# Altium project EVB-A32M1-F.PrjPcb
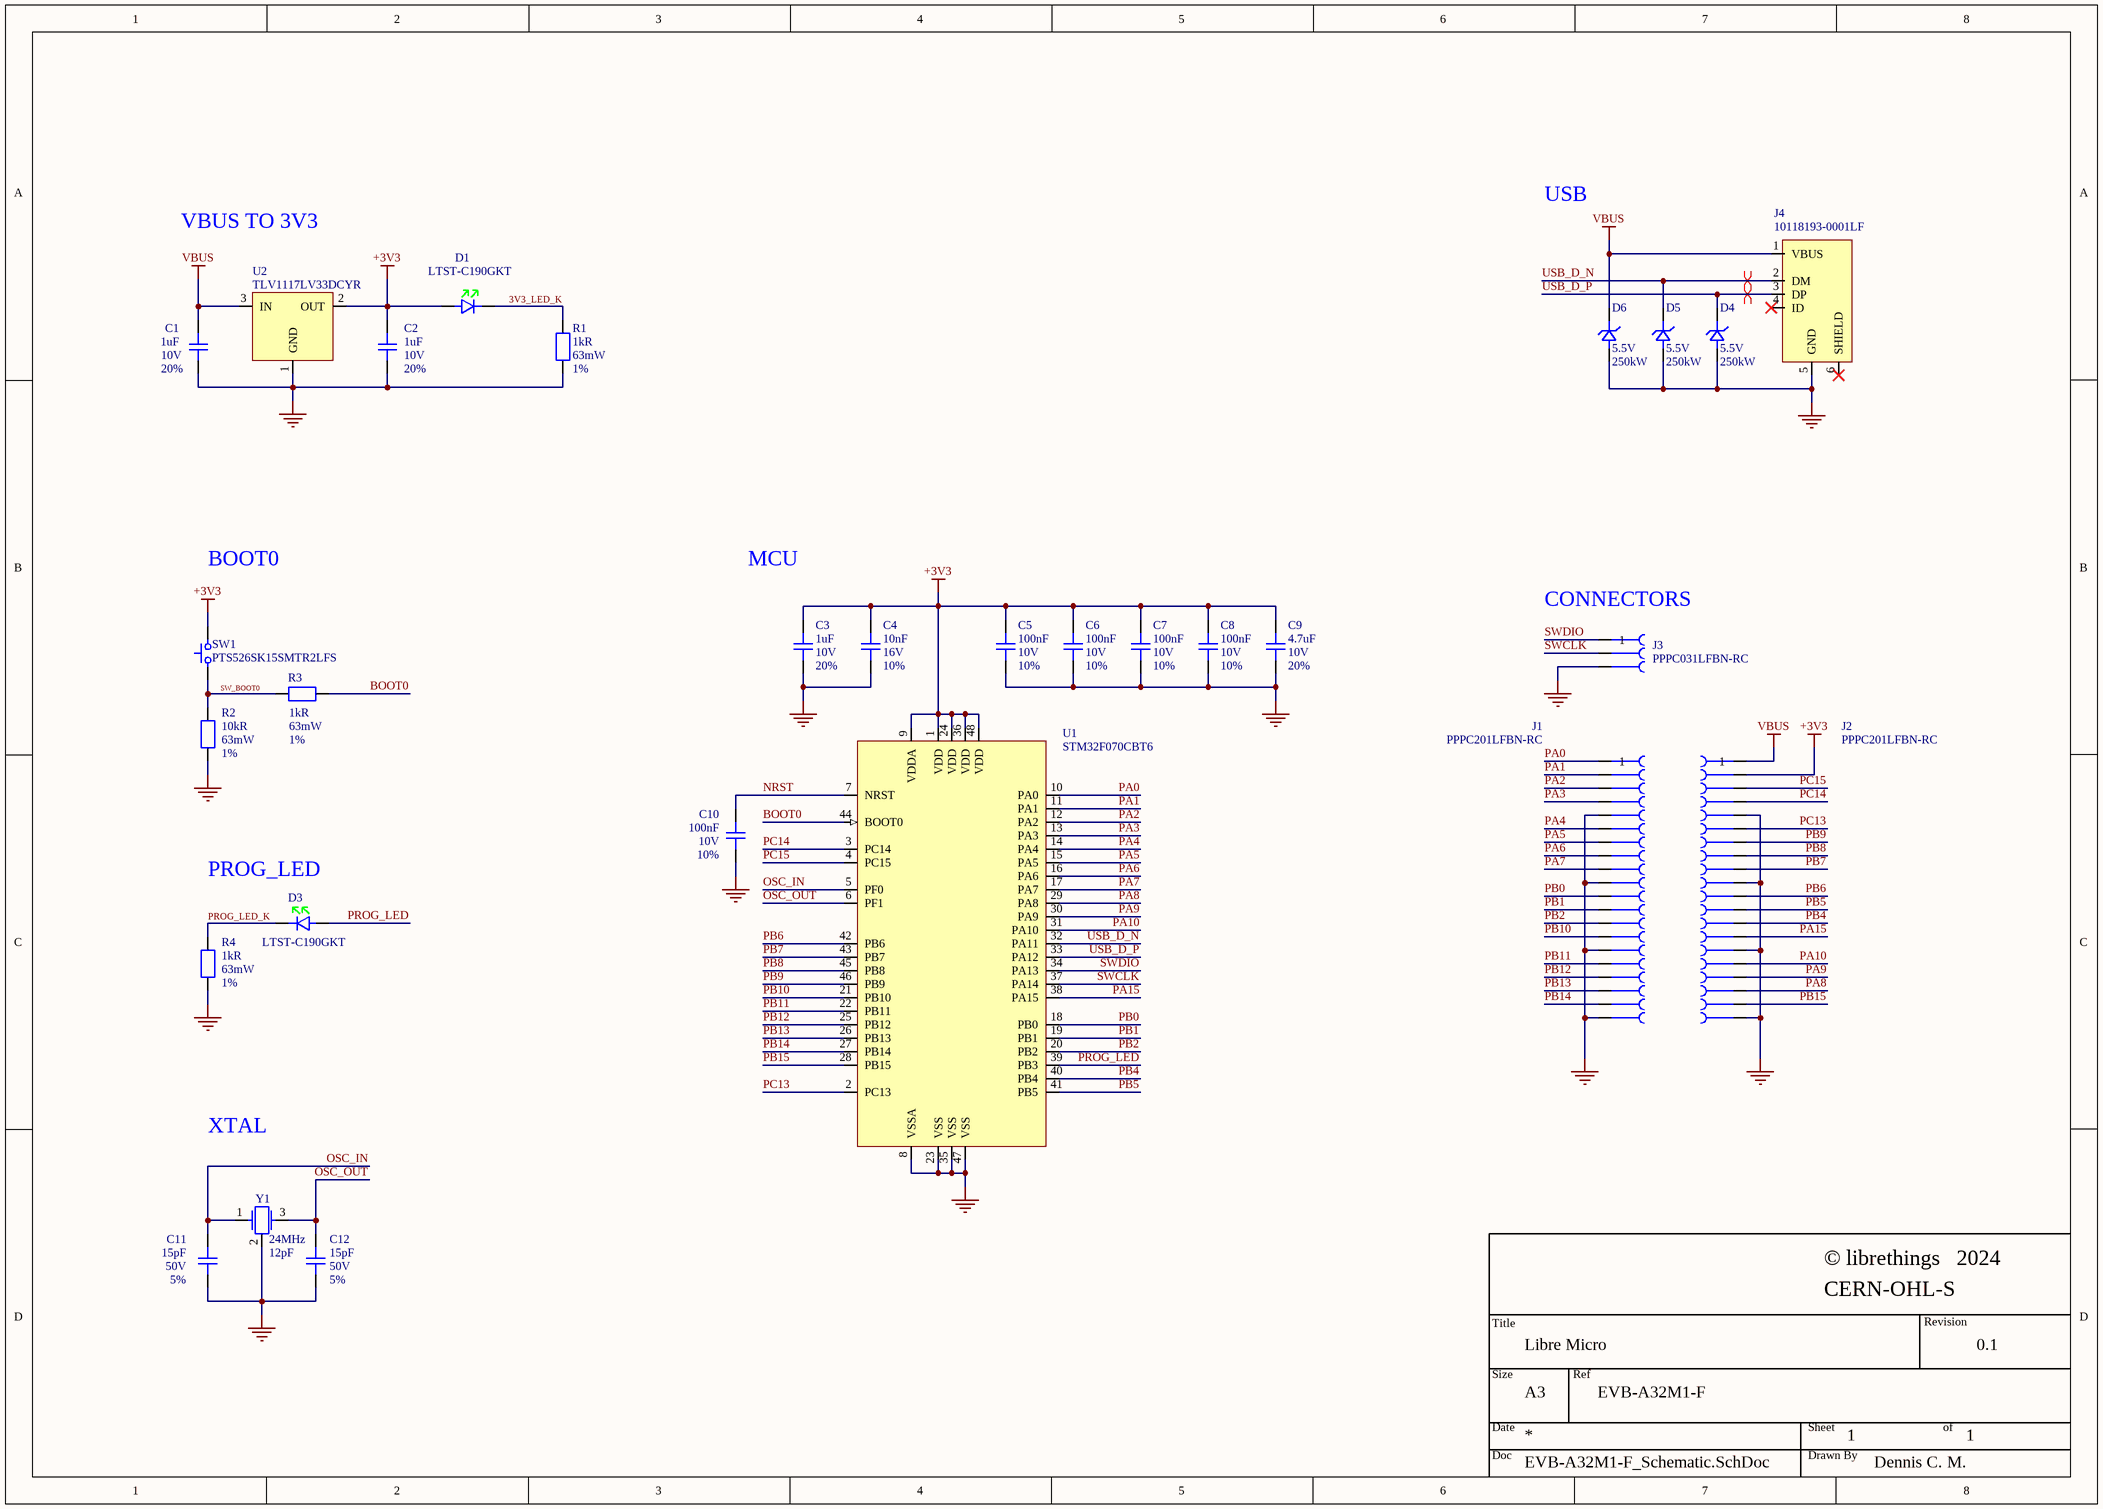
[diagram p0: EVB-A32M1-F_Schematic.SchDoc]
CompanyName: Librethings; CopyrightYear: 2024; DrawnBy: Dennis C. M.; License: CERN-OHL-S; Ref: EVB-A32M1-F; Revision: 0.1; Title: Libre Micro
1 sheet, 29 parts. Net scope: global (net labels, ports and power ports of the same name join across sheets).
Board files: EVB-A32M1-F_PCB.PcbDoc, EVB-A32M1-F_PCB_Doc.PcbDoc

## Sheet EVB-A32M1-F_Schematic.SchDoc: Libre Micro
size A3; SheetNumber: 1; SheetTotal: 1; Size: A4

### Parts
C1  value 1uF  Voltage Rating (DC): 10V  Tolerance: 20%  [C_Yageo_CC_0402_A]  (hidden comment: CC0402MRX5R6BB105)
C2  value 1uF  Voltage Rating (DC): 10V  Tolerance: 20%  [C_Yageo_CC_0402_A]  (hidden comment: CC0402MRX5R6BB105)
C3  value 1uF  Voltage Rating (DC): 10V  Tolerance: 20%  [C_Yageo_CC_0402_A]  (hidden comment: CC0402MRX5R6BB105)
C4  value 10nF  Tolerance: 10%  Voltage Rating: 16V  [C_Yageo_CC_0402_A]  (hidden comment: CC0402KRX7R7BB103)
C5  value 100nF  Voltage Rating (DC): 10V  Tolerance: 10%  [C_Samsung_CL_0402_A]  (hidden comment: CL05B104KP5NNNC)
C6  value 100nF  Voltage Rating (DC): 10V  Tolerance: 10%  [C_Samsung_CL_0402_A]  (hidden comment: CL05B104KP5NNNC)
C7  value 100nF  Voltage Rating: 10V  Tolerance: 10%  [C_Samsung_CL_0402_A]  (hidden comment: CL05B104KP5NNNC)
C8  value 100nF  Voltage Rating: 10V  Tolerance: 10%  [C_Samsung_CL_0402_A]  (hidden comment: CL05B104KP5NNNC)
C9  value 4.7uF  Tolerance: 20%  Voltage Rating: 10V  [C_Samsung_CL_0402_A]  (hidden comment: CL05A475MP5NRNC)
C10  value 100nF  Voltage Rating (DC): 10V  Tolerance: 10%  [C_Samsung_CL_0402_A]  (hidden comment: CL05B104KP5NNNC)
C11  value 15pF  Tolerance: 5%  Voltage Rating: 50V  [C_Yageo_CC_0402_A]  (hidden comment: CC0402JRNPO9BN150)
C12  value 15pF  Tolerance: 5%  Voltage Rating: 50V  [C_Yageo_CC_0402_A]  (hidden comment: CC0402JRNPO9BN150)
D1  LTST-C190GKT  [D_LED_Lite-On_Green_0603_A]
D3  LTST-C190GKT  [D_LED_Lite-On_Green_0603_A]
D4  Reverse Standoff Voltage: 5.5V  Peak Pulse Power: 250kW  [D_TVS_Uni_Diodes_SOD-923_B]  (hidden comment: D5V0F1U2S9-7)
D5  Reverse Standoff Voltage: 5.5V  Peak Pulse Power: 250kW  [D_TVS_Uni_Diodes_SOD-923_B]  (hidden comment: D5V0F1U2S9-7)
D6  Reverse Standoff Voltage: 5.5V  Peak Pulse Power: 250kW  [D_TVS_Uni_Diodes_SOD-923_B]  (hidden comment: D5V0F1U2S9-7)
J1  PPPC201LFBN-RC  [J_Cast_TH20_Top_2.54mm]
J2  PPPC201LFBN-RC  [J_Cast_TH20_Bottom_2.54mm]
J3  PPPC031LFBN-RC  [J_Cast_TH3_Bottom_2.54mm]
J4  10118193-0001LF  [J_USB_Micro-B_Amphenol_10118193-0001LF]
R1  value 1kR  Max Power Dissipation: 63mW  Resistance Tolerance: 1%  [R_Yageo_RCL_0402_A]  (hidden comment: RC0402FR-071KL)
R2  value 10kR  Resistance Tolerance: 1%  Max Power Dissipation: 63mW  [R_Yageo_RCL_0402_A]  (hidden comment: RC0402FR-0710KL)
R3  value 1kR  Max Power Dissipation: 63mW  Resistance Tolerance: 1%  [R_Yageo_RCL_0402_A]  (hidden comment: RC0402FR-071KL)
R4  value 1kR  Max Power Dissipation: 63mW  Resistance Tolerance: 1%  [R_Yageo_RCL_0402_A]  (hidden comment: RC0402FR-071KL)
SW1  PTS526SK15SMTR2LFS  [SW_Tactitle_SPST_C&K_PTS526 SK15 SMTR2 LFS]
U1  STM32F070CBT6  [U_ST_LQFP48_B]
U2  TLV1117LV33DCYR  [U_TI_SOT-223_B]
Y1  Frequency: 24MHz  Load Capacitance: 12pF  [Y_Crystal_GND24_ECS_240-12-37B-CKY-TR]  (hidden comment: ECS-240-12-37B-CKY-TR)

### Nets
+3V3: C2.2 C3.2 C4.2 C5.2 C6.2 C7.2 C8.2 C9.2 D1.2 J2.2 SW1.2 U1.1(VDD) U1.9(VDDA) U1.24(VDD) U1.36(VDD) U1.48(VDD) U2.2(OUT)
GND: C1.1 C2.1 C3.1 C4.1 C5.1 C6.1 C7.1 C8.1 C9.1 C10.1 C11.1 C12.1 D4.2 D5.2 D6.2 J1.5 J1.10 J1.15 J1.20 J2.5 J2.10 J2.15 J2.20 J3.3 J4.5(GND) R1.1 R2.1 R4.1 U1.8(VSSA) U1.23(VSS) U1.35(VSS) U1.47(VSS) U2.1(GND) Y1.2
VBUS: C1.2 D6.1 J2.1 J4.1(VBUS) U2.3(IN)
3V3_LED_K: D1.1 R1.2
BOOT0: R3.1 U1.44(BOOT0)
NRST: C10.2 U1.7(NRST)
OSC_IN: C11.2 U1.5(PF0) Y1.1
OSC_OUT: C12.2 U1.6(PF1) Y1.3
PA0: J1.1 U1.10(PA0)
PA1: J1.2 U1.11(PA1)
PA2: J1.3 U1.12(PA2)
PA3: J1.4 U1.13(PA3)
PA4: J1.6 U1.14(PA4)
PA5: J1.7 U1.15(PA5)
PA6: J1.8 U1.16(PA6)
PA7: J1.9 U1.17(PA7)
PA8: J2.18 U1.29(PA8)
PA9: J2.17 U1.30(PA9)
PA10: J2.16 U1.31(PA10)
PA15: J2.14 U1.38(PA15)
PB0: J1.11 U1.18(PB0)
PB1: J1.12 U1.19(PB1)
PB2: J1.13 U1.20(PB2)
PB4: J2.13 U1.40(PB4)
PB5: J2.12 U1.41(PB5)
PB6: J2.11 U1.42(PB6)
PB7: J2.9 U1.43(PB7)
PB8: J2.8 U1.45(PB8)
PB9: J2.7 U1.46(PB9)
PB10: J1.14 U1.21(PB10)
PB11: J1.16 U1.22(PB11)
PB12: J1.17 U1.25(PB12)
PB13: J1.18 U1.26(PB13)
PB14: J1.19 U1.27(PB14)
PB15: J2.19 U1.28(PB15)
PC13: J2.6 U1.2(PC13)
PC14: J2.4 U1.3(PC14)
PC15: J2.3 U1.4(PC15)
PROG_LED: D3.2 U1.39(PB3)
PROG_LED_K: D3.1 R4.2
SW_BOOT0: R2.2 R3.2 SW1.1
SWCLK: J3.2 U1.37(PA14)
SWDIO: J3.1 U1.34(PA13)
USB_D_N: D5.1 J4.2(DM) U1.32(PA11)
USB_D_P: D4.1 J4.3(DP) U1.33(PA12)

Not connected (* = marked no-connect by the designer): J4 4(ID)* 6(SHIELD)*

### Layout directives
differential pair; differential pair class DIFF_USB: USB_D_N, USB_D_P

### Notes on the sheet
- VBUS TO 3V3
- USB
- BOOT0
- MCU
- (near J3) CONNECTORS
- (near D3) PROG_LED
- XTAL

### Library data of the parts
C1-C3 = CMP-001-00016-11: Multilayer Ceramic Capacitor, 1 uF, 50 V, ± 10%, X5R, 0402 [1005 Metric]; Temperature Coefficient: 30ppm/°C
C4 = CMP-001-00029-1: Multilayer Ceramic Capacitor, 0.01 uF, 16 V, ± 10%, X7R, 0402 [1005 Metric]; Dissipation Factor: 3.5%; Temperature Coefficient: 30ppm/°C; Insulation Resistance: 10GR
C5-C8 C10 = CMP-001-00023-3: Multilayer Ceramic Capacitor, 0.1 uF, 10 V, ± 10%, X7R, 0402 [1005 Metric]
C9 = CMP-001-00024-3: Multilayer Ceramic Capacitor, 4.7 uF, 10 V, ± 20%, X5R, 0402 [1005 Metric]
C11 C12 = CMP-001-00017-14: Multilayer Ceramic Capacitor, 15 pF, 10 V, ± 5%, X7R, 0402 [1005 Metric]; Temperature Coefficient: 30ppm/°C; Dielectric: C0G; Insulation Resistance: 100GR
D1 D3 = CMP-007-00001-3: LED Uni-Color Green 565nm 2-Pin Chip LED T/R; Dominant Wavelength: 569nm; Forward Current: 30mA; Reverse Voltage: 5V; Lens Transparency: Clear; Power Dissipation: 100mW; Number of Elements: 1; Viewing Angle: 130°; Test Current: 10mA; Forward Voltage: 2.1V; Lens Color: Colorless; Voltage: 2V; Lens Size: 0.8mm; Lens Style: Flat,Diffused,Colorless,Rectangular,Clear; Luminous Intensity: 6mcd
D4-D6 = CMP-004-00007-2: Diode TVS Dual Uni-Dir 5.5V 250000W 2-Pin SOD-923 T/R; Max Reverse Leakage Current: 100nA; Number of Unidirectional Channels: 1; ESD Protection: Yes; Diode Type: ZENER; Max Surge Current: 1.5A; Min Breakdown Voltage: 6V; Polarity: Unidirectional; Value: 5E-13F; Max Power Dissipation: 250mW; Clamping Voltage: 10V
J1 J2 = CMP-002-00009-9: 20 Position Total Single Row 2.54 mm Pitch Straight Female Header; pin to pad: 1>1+1T+1B 2>2+2T+2B 3>3+3T+3B 4>4+4T+4B 5>5+5T+5B 6>6+6T+6B 7>7+7T+7B 8>8+8T+8B 9>9+9T+9B 10>10+10T+10B 11>11+11T+11B 12>12+12T+12B 13>13+13T+13B 14>14+14T+14B 15>15+15T+15B 16>16+16T+16B 17>17+17T+17B 18>18+18T+18B 19>19+19T+19B 20>20+20T+20B; Pitch: 2.54mm; Number of Positions: 20; Voltage Rating: 250V
J3 = CMP-002-00004-17: 3 Position Total Single Row 2.54 mm Pitch Straight Female Header; pin to pad: 1>1+1T+1B 2>2+2T+2B 3>3+3T+3B; Number of Positions: 3; Voltage Rating: 250V; Pitch: 2.54mm
J4 = CMP-002-00002-12: Usb Connector, 5 Contact(S), Female, Right Angle, Surface Mount Terminal, Locking, Receptacle; Max Voltage Rating (AC): 100V; USB Standard: USB 2.0; Connector Type: USB,Receptacle; Number of Contacts: 5; Number of Ports: 1; Insulation Resistance: 1GR; Pitch: 650um; Current Rating: 1.8A
R1 R3 R4 = CMP-009-00002-11: SMD Chip Resistor, 1 kOhm, ± 1%, 62.5 mW, 0402 [1005 Metric], Thick Film, General Purpose; Temperature Coefficient: 100ppm/°C; Voltage Rating (AC): 50V; Power Rating: 62.5mW
R2 = CMP-009-00003-11: SMD Chip Resistor, 10 kOhm, ± 1%, 62.5 mW, 0402 [1005 Metric], Thick Film, General Purpose; Voltage Rating (DC): 50V; Temperature Coefficient: 100ppm/°C; Power Rating: 62.5mW
SW1 = CMP-011-00002-2: Switch Tactile N.O. SPST Round Button Gull Wing 0.05A 12VDC 200000Cycles 2.45N SMD T/R; pin to pad: 1>1+2 2>3+4; Number of Positions: 2; Operating Force: 260gf; Actuator Type: Standard; Illumination Type: Non-Illuminated; Switch Function: Off-Mom; Switch Travel: 0.25mm; Ratings: IP40; Contact Current Rating: 50mA; Contact Resistance: 100mR; Voltage Rating (DC): 12V
U1 = CMP-020-00002-1: IC MCU 32BIT 128KB FLASH 48LQFP; Operating Supply Voltage: 3.3V; Peripherals: POR,PWM,WDT,DMA; Number of I/Os: 37; Data Bus Width: 32b; Min Supply Voltage: 2.4V; Number of Timers/Counters: 8; Interface: I2C,SPI,USB,UART,USART; Max Supply Voltage: 3.6V; Core Architecture: ARM; Watchdog Timer: Yes; Max Power Dissipation: 364mW; Clock Frequency: 48MHz; RAM Size: 16KB; Number of ADC Channels: 1; Oscillator Type: Internal
U2 = CMP-019-00002-2: LDO Regulator Pos 3.3V 1A 4-Pin(3+Tab) SOT-223 T/R; pin to pad: 2>2+4; Output Type: Fixed; Power Supply Rejection Ratio (PSRR): 75dB; Polarity: Positive; Dropout Voltage: 570mV; Quiescent Current: 50uA; Max Supply Voltage: 5.5V; Accuracy: 2%; Number of Regulators: 1; Min Input Voltage: 2V
Y1 = CMP-003-00000-11: Crystal 24MHz ±10ppm (Tol) ±10ppm (Stability) 12pF FUND 50Ohm 4-Pin Mini-CSMD T/R; pin to pad: 2>2+4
